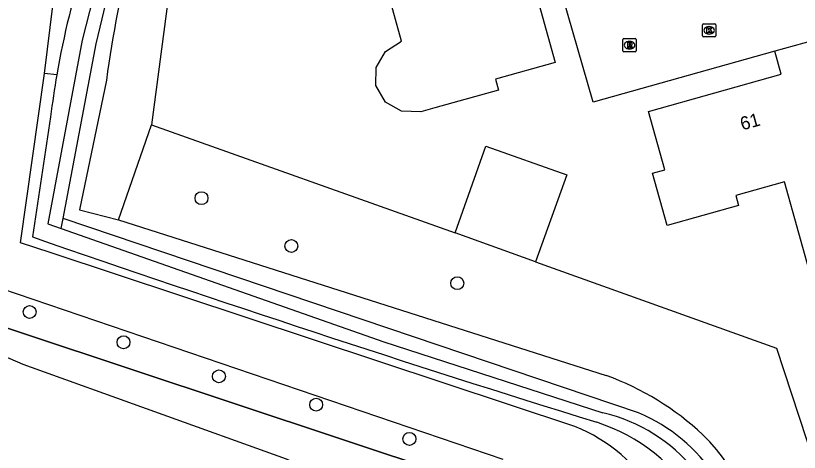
# Model space of a CAD drawing. Extents: x 159628 to 160723, y 388176 to 389416.
# Drawn here: x 159782.2 to 159841.5, y 388387.1 to 388420.2 of the extents above; entities that cross this region are included whole.
import ezdxf

# ---------------------------------------------------------------- set-up
doc = ezdxf.new("R2010")
doc.units = 0
for name, color, linetype in [('IMGEO_Boom', 7, 'Continuous'), ('IMGEO_Bouwland', 7, 'Continuous'), ('IMGEO_Grasland_overig', 7, 'Continuous'), ('IMGEO_Groenvoorziening', 7, 'Continuous'), ('IMGEO_Hek', 7, 'Continuous'), ('IMGEO_Kolk', 7, 'Continuous'), ('IMGEO_Pand', 7, 'Continuous'), ('IMGEO_Pand_nummerreeks', 7, 'Continuous'), ('IMGEO_Rijbaan_lokaal_onverhard', 7, 'Continuous'), ('IMGEO_Rijbaan_lokaal_open', 7, 'Continuous'), ('IMGEO_Rioolput', 7, 'Continuous'), ('IMGEO_Waterloop', 7, 'Continuous')]:
    doc.layers.add(name, color=color, linetype=linetype)

msp = doc.modelspace()

# ---------------------------------------------------------------- linework, layer by layer
at = {"layer": 'IMGEO_Boom'}
for centre in [(159796.244, 388406.353), (159803.051, 388402.727), (159815.619, 388399.912), (159783.226, 388397.735), (159790.34, 388395.438), (159797.566, 388392.858), (159804.93, 388390.711), (159811.993, 388388.121)]:
    msp.add_circle(centre, 0.489, dxfattribs=at)
at = {"layer": 'IMGEO_Bouwland'}
msp.add_lwpolyline([(159815.115, 388340.78), (159807.897, 388340.56), (159783.84, 388356.314), (159761.756, 388337.982), (159758.218, 388336.91), (159755.324, 388337.875), (159726.7, 388366.927), (159730.667, 388375.611), (159743.638, 388389.761), (159753.126, 388400.643), (159756.556, 388403.966), (159759.773, 388404.073), (159764.382, 388402.519), (159773.066, 388397.962), (159782.714, 388393.782), (159802.654, 388386.599), (159809.515, 388383.49), (159817.805, 388380.266)], dxfattribs=at)
at = {"layer": 'IMGEO_Grasland_overig'}
msp.add_lwpolyline([(159776.009, 388404.236), (159775.007, 388400.272), (159774.766, 388398.746), (159814.819, 388385.452), (159818.335, 388384.285)], dxfattribs=at)
at = {"layer": 'IMGEO_Groenvoorziening'}
for points in [[(159814.541, 388454.32), (159807.997, 388451.759), (159805.65, 388447.79), (159803.03, 388444.48), (159801.04, 388441.03), (159797.51, 388433.94), (159794.66, 388426.63), (159793.923, 388423.023), (159792.464, 388411.905)], [(159785.289, 388415.704), (159784.358, 388415.796)], [(159789.039, 388415.299), (159787.007, 388405.479), (159789.962, 388404.704)], [(159784.81, 388412.513), (159783.45, 388403.414)], [(159789.962, 388404.704), (159792.464, 388411.905)], [(159792.464, 388411.905), (159815.456, 388403.719)], [(159789.962, 388404.704), (159826.902, 388392.927)], [(159821.548, 388401.54), (159839.802, 388394.99), (159844.918, 388379.382), (159842.558, 388360.271)]]:
    msp.add_lwpolyline(points, dxfattribs=at)
for centre, radius, start, end in [((159890.097, 388401.269), 102.027, 160.45448, 172.09617), ((159853.556, 388403.813), 69.295, 162.61105, 170.11897), ((159853.992, 388403.76), 69.734, 170.13737, 172.78881), ((160231.839, 389696.589), 1368.705, 250.876757, 252.760017), ((159819.419, 388372.505), 21.75, 47.10531, 69.87551), ((159821.916, 388376.188), 13.864, 30.85824, 72.04599), ((159824.856, 388378.737), 13.486, 355.11348, 46.00671)]:
    msp.add_arc(centre, radius, start, end, dxfattribs=at)
at = {"layer": 'IMGEO_Hek'}
msp.add_lwpolyline([(159814.819, 388385.452), (159774.766, 388398.746), (159775.007, 388400.272), (159776.435, 388405.923)], dxfattribs=at)
at = {"layer": 'IMGEO_Kolk'}
for p, q in [((159834.195, 388418.638), (159834.195, 388419.49)), ((159834.27, 388419.564), (159835.122, 388419.564)), ((159834.683, 388419.344), (159834.708, 388419.344)), ((159835.196, 388419.49), (159835.196, 388418.638)), ((159834.706, 388418.784), (159834.681, 388418.784)), ((159835.122, 388418.564), (159834.27, 388418.564))]:
    msp.add_line(p, q, dxfattribs=at)
for points in [[(159834.195, 388418.638), (159834.195, 388419.49)], [(159834.27, 388419.564), (159835.122, 388419.564)], [(159834.516, 388419.264), (159834.639, 388419.264), (159834.639, 388419.113), (159834.769, 388419.264), (159834.933, 388419.264), (159834.787, 388419.113), (159834.94, 388418.864), (159834.788, 388418.864), (159834.703, 388419.028), (159834.639, 388418.961), (159834.639, 388418.864), (159834.516, 388418.864), (159834.516, 388419.264)], [(159835.196, 388419.49), (159835.196, 388418.638)], [(159835.122, 388418.564), (159834.27, 388418.564)]]:
    msp.add_lwpolyline(points, dxfattribs=at)
for centre, start, end in [((159834.272, 388419.488), 91.55205, 178.44795), ((159834.272, 388419.488), 91.55205, 178.44795), ((159835.12, 388419.488), 1.55205, 88.44795), ((159835.12, 388419.488), 1.55205, 88.44795), ((159834.272, 388418.64), 181.55205, 268.44795), ((159834.272, 388418.64), 181.55205, 268.44795), ((159835.12, 388418.64), 271.55205, 358.44795), ((159835.12, 388418.64), 271.55205, 358.44795)]:
    msp.add_arc(centre, 0.0765, start, end, dxfattribs=at)
for centre, major_axis, ratio, start_param, end_param in [((159834.682, 388419.064), (-0.387, 0.002), 0.722429, 4.712389, 7.853982), ((159834.707, 388419.064), (-0.39, 0.002), 0.717154, 1.570796, 4.712389)]:
    msp.add_ellipse(centre, major_axis=major_axis, ratio=ratio, start_param=start_param, end_param=end_param, dxfattribs=at)
at = {"layer": 'IMGEO_Pand'}
for points in [[(159822.036, 388427.124), (159820.253, 388426.629), (159823.028, 388416.629), (159818.505, 388415.373), (159818.737, 388414.534), (159813.92, 388413.197), (159812.85, 388412.9), (159811.406, 388412.946), (159810.18, 388413.622), (159809.462, 388414.887), (159809.479, 388416.25), (159810.179, 388417.462), (159811.393, 388418.244), (159810.35, 388422.002), (159810.639, 388422.082), (159809.375, 388426.638)], [(159843.335, 388418.506), (159839.667, 388417.477)], [(159848.169, 388401.396), (159842.588, 388399.819), (159840.393, 388407.588), (159836.707, 388406.547), (159836.918, 388405.801), (159831.526, 388404.288), (159830.419, 388408.236), (159831.334, 388408.492), (159830.091, 388412.921), (159840.153, 388415.744), (159839.667, 388417.477)], [(159815.456, 388403.719), (159817.788, 388410.298), (159823.907, 388408.128), (159821.548, 388401.54)], [(159821.548, 388401.54), (159815.456, 388403.719)]]:
    msp.add_lwpolyline(points, dxfattribs=at)
at = {"layer": 'IMGEO_Rijbaan_lokaal_onverhard'}
for points in [[(159784.358, 388415.796), (159785.676, 388426.481), (159787.671, 388434.224), (159789.718, 388439.781), (159791.616, 388444.055), (159795.462, 388449.706), (159802.457, 388457.03), (159808.466, 388462.866), (159810.017, 388461.905)], [(159709.699, 388434.611), (159709.699, 388434.611), (159709.845, 388434.552), (159711.227, 388433.998), (159712.6, 388433.494), (159772.692, 388411.435), (159780.026, 388408.959), (159778.697, 388400.322), (159819.062, 388386.574)], [(159824.533, 388389.058), (159784.85, 388402.209), (159782.536, 388402.976), (159784.358, 388415.796)]]:
    msp.add_lwpolyline(points, dxfattribs=at)
msp.add_arc((159819.723, 388377.168), 12.826, 31.19454, 67.97605, dxfattribs=at)
at = {"layer": 'IMGEO_Rijbaan_lokaal_open'}
msp.add_lwpolyline([(159839.667, 388417.477), (159825.91, 388413.624), (159822.036, 388427.124)], dxfattribs=at)
at = {"layer": 'IMGEO_Rioolput'}
for p, q in [((159828.17, 388417.515), (159828.17, 388418.367)), ((159828.245, 388418.441), (159829.097, 388418.441)), ((159828.658, 388418.221), (159828.683, 388418.221)), ((159829.171, 388418.367), (159829.171, 388417.515)), ((159829.097, 388417.441), (159828.245, 388417.441)), ((159828.681, 388417.661), (159828.656, 388417.661))]:
    msp.add_line(p, q, dxfattribs=at)
for points in [[(159828.17, 388417.515), (159828.17, 388418.367)], [(159828.245, 388418.441), (159829.097, 388418.441)], [(159828.759, 388418.139), (159828.507, 388418.141), (159828.507, 388417.741)], [(159828.685, 388418.06), (159828.631, 388418.06), (159828.631, 388417.979)], [(159829.171, 388418.367), (159829.171, 388417.515)], [(159829.097, 388417.441), (159828.245, 388417.441)], [(159828.507, 388417.741), (159828.631, 388417.741), (159828.631, 388417.903), (159828.642, 388417.903)], [(159828.631, 388417.979), (159828.683, 388417.979)], [(159828.689, 388417.874), (159828.76, 388417.741), (159828.9, 388417.741), (159828.835, 388417.867)]]:
    msp.add_lwpolyline(points, dxfattribs=at)
for centre, radius, start, end in [((159828.247, 388418.365), 0.0765, 91.55205, 178.44795), ((159828.247, 388418.365), 0.0765, 91.55205, 178.44795), ((159828.691, 388417.964), 0.0964, 77.00612, 93.18647), ((159828.705, 388418.021), 0.0378, 276.66336, 79.67722), ((159828.758, 388418.029), 0.109, 350.36119, 89.41601), ((159828.756, 388418.029), 0.112, 277.58423, 350.98172), ((159829.095, 388418.365), 0.0765, 1.55205, 88.44795), ((159829.095, 388418.365), 0.0765, 1.55205, 88.44795), ((159828.247, 388417.517), 0.0765, 181.55205, 268.44795), ((159828.247, 388417.517), 0.0765, 181.55205, 268.44795), ((159828.641, 388417.85), 0.0533, 26.02933, 88.69889), ((159828.667, 388418.168), 0.19, 274.7715, 282.96867), ((159828.74, 388417.814), 0.108, 29.51342, 73.79051), ((159829.095, 388417.517), 0.0765, 271.55205, 358.44795), ((159829.095, 388417.517), 0.0765, 271.55205, 358.44795)]:
    msp.add_arc(centre, radius, start, end, dxfattribs=at)
for centre, major_axis, ratio, start_param, end_param in [((159828.657, 388417.941), (-0.387, 0.002), 0.722429, 4.712389, 7.853982), ((159828.682, 388417.941), (-0.39, 0.002), 0.717154, 1.570796, 4.712389)]:
    msp.add_ellipse(centre, major_axis=major_axis, ratio=ratio, start_param=start_param, end_param=end_param, dxfattribs=at)
at = {"layer": 'IMGEO_Waterloop'}
for points in [[(159790.789, 388432.346), (159787.196, 388418.321), (159784.608, 388404.41), (159785.61, 388404.058)], [(159785.768, 388404.81), (159788.263, 388418.034), (159791.672, 388432.284)], [(159785.61, 388404.058), (159785.768, 388404.81)], [(159829.352, 388390.087), (159785.768, 388404.81)], [(159785.61, 388404.058), (159810.05, 388395.467), (159826.641, 388390.087)]]:
    msp.add_lwpolyline(points, dxfattribs=at)
for centre, radius, start, end in [((159823.812, 388377.801), 12.608, 1.52742, 77.03259), ((159824.394, 388378.194), 12.885, 359.19512, 67.37082)]:
    msp.add_arc(centre, radius, start, end, dxfattribs=at)

# ---------------------------------------------------------------- texts
at = {"layer": 'IMGEO_Pand_nummerreeks'}
msp.add_text('61', height=1, rotation=15.50618, dxfattribs=at).set_placement((159837.207, 388411.477))

doc.saveas('drawing.dxf')
